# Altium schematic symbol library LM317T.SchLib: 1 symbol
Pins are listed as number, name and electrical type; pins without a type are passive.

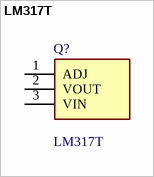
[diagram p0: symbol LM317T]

## LM317T
designator Q?
Linear Voltage Regulator IC Positive Adjustable 1 Output 1.5A TO-220; Manufacturer_Name: Analog Devices; Geometry.Height: 4.699mm
footprint TO254P470X1036X1920-3P
pins: 1 ADJ, 2 VOUT, 3 VIN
